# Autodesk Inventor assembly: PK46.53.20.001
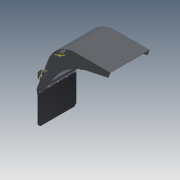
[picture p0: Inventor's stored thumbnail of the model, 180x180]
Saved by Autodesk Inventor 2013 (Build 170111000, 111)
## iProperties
Created: 2005-03
Part Number: PK46.53.20.001
Document SubType Name: Assembly
Designer: tedescj
Manufacturer: Standard
Standards Organization: Custom
Author: HKostja
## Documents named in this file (17)
- D:\FrontLoaderVault\Data\Assy, Chassis, Front\PK46.53.20.001.iam
- D:\FrontLoaderVault\Data\Assy, Chassis, Front\PK46.53.20.001-011.ipt
- D:\FrontLoaderVault\Data\Assy, Chassis, Front\PK46.53.20.002.ipt
- D:\FrontLoaderVault\Data\Assy, Chassis, Front\PK46.53.20.003.ipt
- D:\FrontLoaderVault\Data\Assy, Chassis, Front\PK46.53.20.007.ipt
- D:\FrontLoaderVault\Data\Assy, Chassis, Front\PK46.53.20.004.ipt
- D:\FrontLoaderVault\Data\Assy, Chassis, Front\PK46.53.20.005.ipt
- D:\FrontLoaderVault\Data\Assy, Chassis, Front\M10-6H.5.019(S16).ipt
- D:\FrontLoaderVault\Data\Assy, Chassis, Front\10.65G.019.ipt
- D:\FrontLoaderVault\Data\Assy, Chassis, Front\M10-6gx30.58.019(S16).ipt
- D:\FrontLoaderVault\Data\Assy, Chassis, Front\PK46.53.20.006.ipt
- D:\FrontLoaderVault\Data\Assy, Chassis, Front\PK46.53.20.001.ipt
- PK46.53.20.004.ipt
- PK46.53.20.005.ipt
- M10-6H.5.019(S16).ipt
- 10.65G.019.ipt
- M10-6gx30.58.019(S16).ipt
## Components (26 placed, 11 different names)
1. PK46.53.20.001:1 — Mate:8, Mate:10, Mate:9, Flush:2, Mate:14, Mate:15
2. PK46.53.20.001-011:1 — Mate:13, Flush:3, Mate:7, Mate:16, Mate:22, Mate:17, Mate:21
3. PK46.53.20.002:1 — Mate:13, Mate:8, Mate:10, Flush:3, Mate:9, Flush:2, Mate:7, Mate:20, Insert:3, Insert:20, Angle:2, Angle:1, Insert:24, Insert:23, Insert:22, Insert:21, Mate:22, Mate:23
4. PK46.53.20.003:1 — Mate:16, Mate:14, Insert:2, Tangent:1, Tangent:2
5. PK46.53.20.003:2 — Angle:1, Mate:17, Mate:15, Mate:19, Insert:1, Mate:19, Mate:20
6. PK46.53.20.007:1 — Angle:2, Insert:2
7. PK46.53.20.007:2 — Mate:19, Insert:1
8. PK46.53.20.004:1 — Insert:4, Mate:21, Insert:10, Insert:11, Insert:12, Insert:13, Insert:14
9. PK46.53.20.005:1 — Insert:4, Mate:21, Mate:20, Insert:3
10. M10-6H.5.019(S16):1 — Flush:9, Flush:8, Insert:16
11. M10-6H.5.019(S16):2 — Flush:9, Flush:10, Insert:17
12. M10-6H.5.019(S16):3 — Flush:10, Flush:11, Insert:18
13. M10-6H.5.019(S16):4 — Flush:11, Insert:19
14. M10-6H.5.019(S16):5 — Flush:8, Insert:15
15. 10.65G.019:1 — Insert:10, Insert:19
16. 10.65G.019:2 — Insert:18, Insert:11
17. 10.65G.019:3 — Insert:17, Insert:12
18. 10.65G.019:4 — Insert:15, Insert:13
19. 10.65G.019:5 — Insert:16, Insert:14
20. M10-6gx30.58.019(S16):1 — Insert:20, Flush:7
21. M10-6gx30.58.019(S16):2 — Flush:7, Flush:6, Insert:21
22. M10-6gx30.58.019(S16):3 — Flush:5, Insert:22, Flush:6
23. M10-6gx30.58.019(S16):4 — Flush:4, Insert:23, Flush:5
24. M10-6gx30.58.019(S16):5 — Insert:24, Flush:4
25. PK46.53.20.006:1 — Mate:22, Mate:19, Tangent:1, Mate:20
26. PK46.53.20.006:2 — Mate:21, Mate:22, Tangent:2, Mate:23
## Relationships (51: Mate 20, Insert 19, Flush 8, Angle 2, Tangent 2)
- Mate:13: PK46.53.20.001-011:1 ↔ PK46.53.20.002:1
- Mate:8: PK46.53.20.001:1 ↔ PK46.53.20.002:1
- Mate:10: PK46.53.20.001:1 ↔ PK46.53.20.002:1
- Flush:3 [Mate]: PK46.53.20.001-011:1 ↔ PK46.53.20.002:1
- Mate:9: PK46.53.20.001:1 ↔ PK46.53.20.002:1
- Flush:2 [Mate]: PK46.53.20.001:1 ↔ PK46.53.20.002:1
- Mate:7: PK46.53.20.001-011:1 ↔ PK46.53.20.002:1
- Mate:16: PK46.53.20.001-011:1 ↔ PK46.53.20.003:1
- Mate:14: PK46.53.20.001:1 ↔ PK46.53.20.003:1
- Insert:4: PK46.53.20.004:1 ↔ PK46.53.20.005:1
- Mate:21: PK46.53.20.004:1 ↔ PK46.53.20.005:1
- Mate:20: PK46.53.20.002:1 ↔ PK46.53.20.005:1
- Insert:3: PK46.53.20.002:1 ↔ PK46.53.20.005:1
- Insert:10: PK46.53.20.004:1 ↔ 10.65G.019:1
- Insert:20: PK46.53.20.002:1 ↔ M10-6gx30.58.019(S16):1
- Mate:22: PK46.53.20.001-011:1 ↔ PK46.53.20.006:1
- Angle:2: PK46.53.20.002:1 ↔ PK46.53.20.007:1
- Insert:2: PK46.53.20.003:1 ↔ PK46.53.20.007:1
- Angle:1: PK46.53.20.002:1 ↔ PK46.53.20.003:2
- Mate:17: PK46.53.20.001-011:1 ↔ PK46.53.20.003:2
- Mate:15: PK46.53.20.001:1 ↔ PK46.53.20.003:2
- Mate:19: PK46.53.20.003:2 ↔ PK46.53.20.007:2
- Insert:1: PK46.53.20.003:2 ↔ PK46.53.20.007:2
- Insert:24: PK46.53.20.002:1 ↔ M10-6gx30.58.019(S16):5
- Flush:4: M10-6gx30.58.019(S16):4 ↔ M10-6gx30.58.019(S16):5
- Insert:23: PK46.53.20.002:1 ↔ M10-6gx30.58.019(S16):4
- Flush:5: M10-6gx30.58.019(S16):3 ↔ M10-6gx30.58.019(S16):4
- Insert:22: PK46.53.20.002:1 ↔ M10-6gx30.58.019(S16):3
- Flush:7: M10-6gx30.58.019(S16):1 ↔ M10-6gx30.58.019(S16):2
- Flush:6: M10-6gx30.58.019(S16):2 ↔ M10-6gx30.58.019(S16):3
- Insert:21: PK46.53.20.002:1 ↔ M10-6gx30.58.019(S16):2
- Flush:9: M10-6H.5.019(S16):1 ↔ M10-6H.5.019(S16):2
- Flush:10: M10-6H.5.019(S16):2 ↔ M10-6H.5.019(S16):3
- Flush:11: M10-6H.5.019(S16):3 ↔ M10-6H.5.019(S16):4
- Insert:19: M10-6H.5.019(S16):4 ↔ 10.65G.019:1
- Flush:8: M10-6H.5.019(S16):1 ↔ M10-6H.5.019(S16):5
- Insert:18: M10-6H.5.019(S16):3 ↔ 10.65G.019:2
- Insert:11: PK46.53.20.004:1 ↔ 10.65G.019:2
- Insert:17: M10-6H.5.019(S16):2 ↔ 10.65G.019:3
- Insert:12: PK46.53.20.004:1 ↔ 10.65G.019:3
- Insert:15: M10-6H.5.019(S16):5 ↔ 10.65G.019:4
- Insert:13: PK46.53.20.004:1 ↔ 10.65G.019:4
- Insert:16: M10-6H.5.019(S16):1 ↔ 10.65G.019:5
- Insert:14: PK46.53.20.004:1 ↔ 10.65G.019:5
- Mate:19: PK46.53.20.003:2 ↔ PK46.53.20.006:1
- Tangent:1: PK46.53.20.003:1 ↔ PK46.53.20.006:1
- Mate:20: PK46.53.20.003:2 ↔ PK46.53.20.006:1
- Mate:21: PK46.53.20.001-011:1 ↔ PK46.53.20.006:2
- Mate:22: PK46.53.20.002:1 ↔ PK46.53.20.006:2
- Tangent:2: PK46.53.20.003:1 ↔ PK46.53.20.006:2
- Mate:23: PK46.53.20.002:1 ↔ PK46.53.20.006:2
